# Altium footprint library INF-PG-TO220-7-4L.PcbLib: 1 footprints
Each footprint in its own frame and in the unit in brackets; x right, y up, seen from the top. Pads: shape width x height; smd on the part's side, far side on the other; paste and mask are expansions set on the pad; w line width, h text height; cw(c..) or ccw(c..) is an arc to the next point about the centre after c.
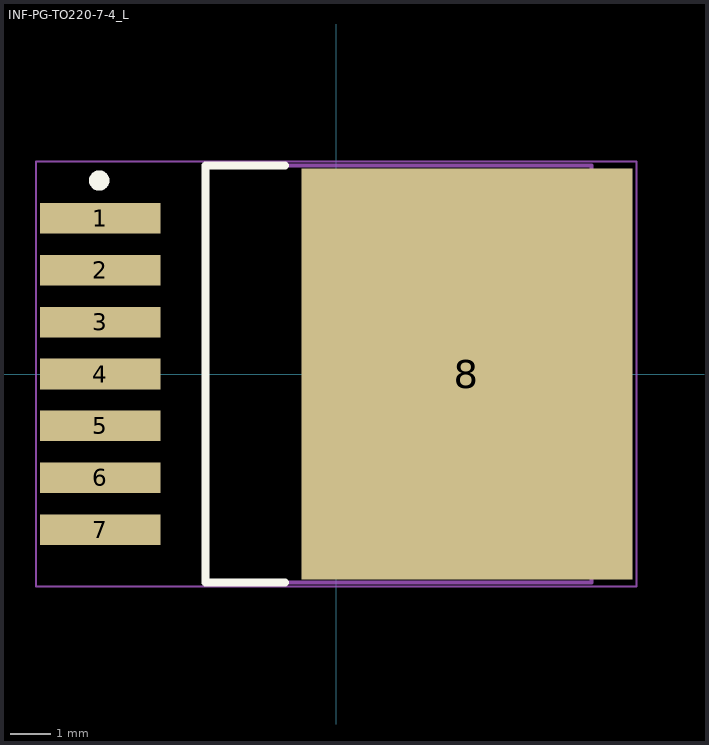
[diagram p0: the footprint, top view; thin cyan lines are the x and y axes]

## INF-PG-TO220-7-4_L [mm] "DPAK, 7-Leads, Body 10x9.25mm, Pitch 1.27mm, IPC High Density"
height 4.4
pads (8):
  rect 2.95x0.75 smd: 1(-5.77,3.81) 2(-5.77,2.54) 3(-5.77,1.27) 4(-5.77,0) 5(-5.77,-1.27) 6(-5.77,-2.54) 7(-5.77,-3.81)
  rect 8.1x10.05 smd: 8(3.2,0)
Top Overlay:
  circle w0.25: c-5.8,4.735 r0.125
  lines w0.2: -1.25,-5.1 -3.2,-5.1 -3.2,5.1 -1.25,5.1
Mechanical 13:
  lines w0.1: -3.2,-5.1 6.25,-5.1 6.25,5.1 -3.2,5.1 -3.2,-5.1
Mechanical 15:
  lines w0.05: -7.35,-5.2 7.35,-5.2 7.35,5.2 -7.35,5.2 -7.35,-5.2
  lines w0.1: -0.5,0 0.5,0 ; 0,-0.5 0,0.5
3D body: height 4.4, standoff 0.1, extent -3.2,-5.1 6.25,5.1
